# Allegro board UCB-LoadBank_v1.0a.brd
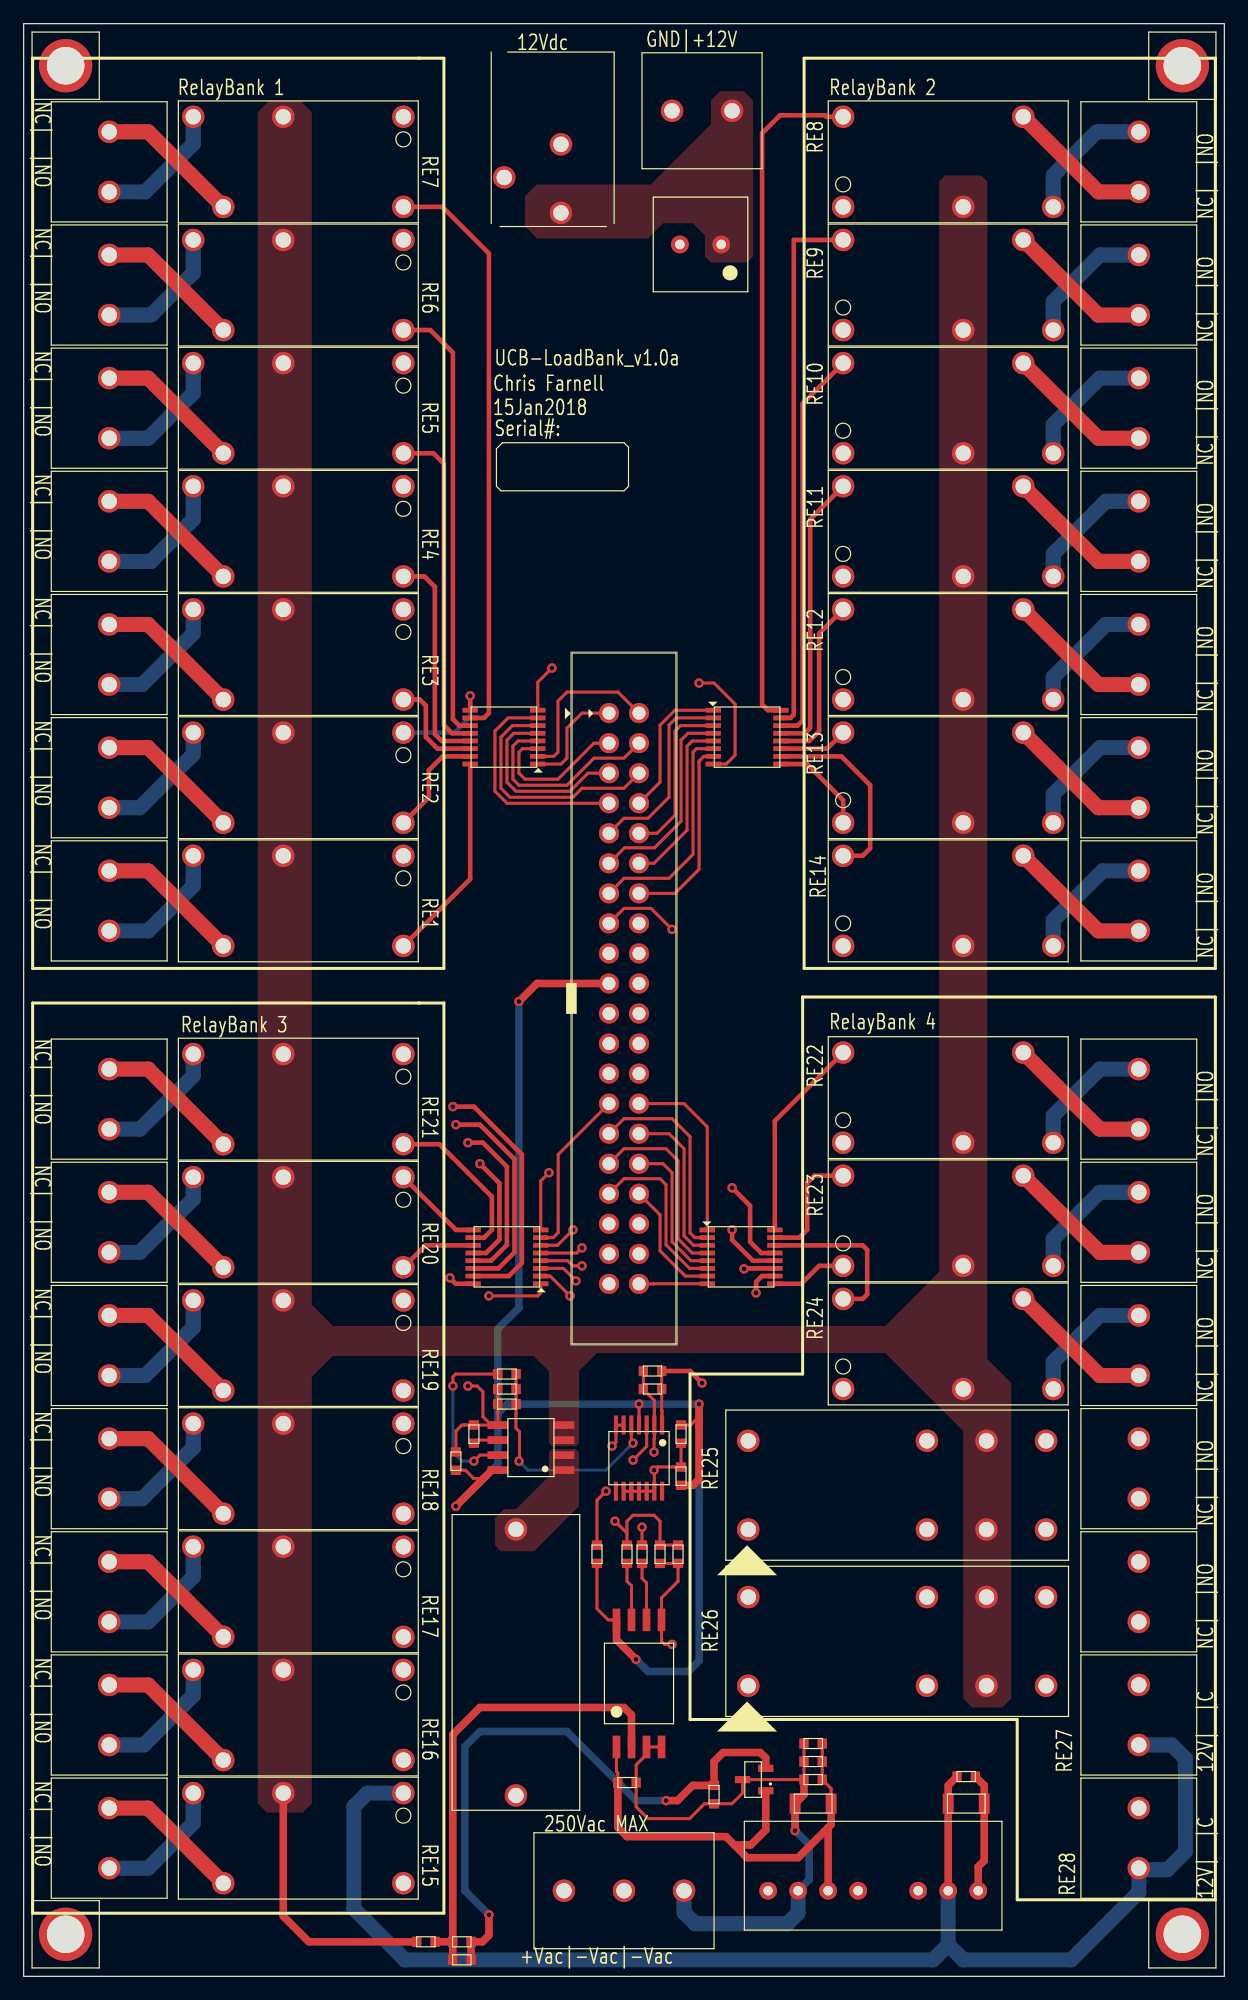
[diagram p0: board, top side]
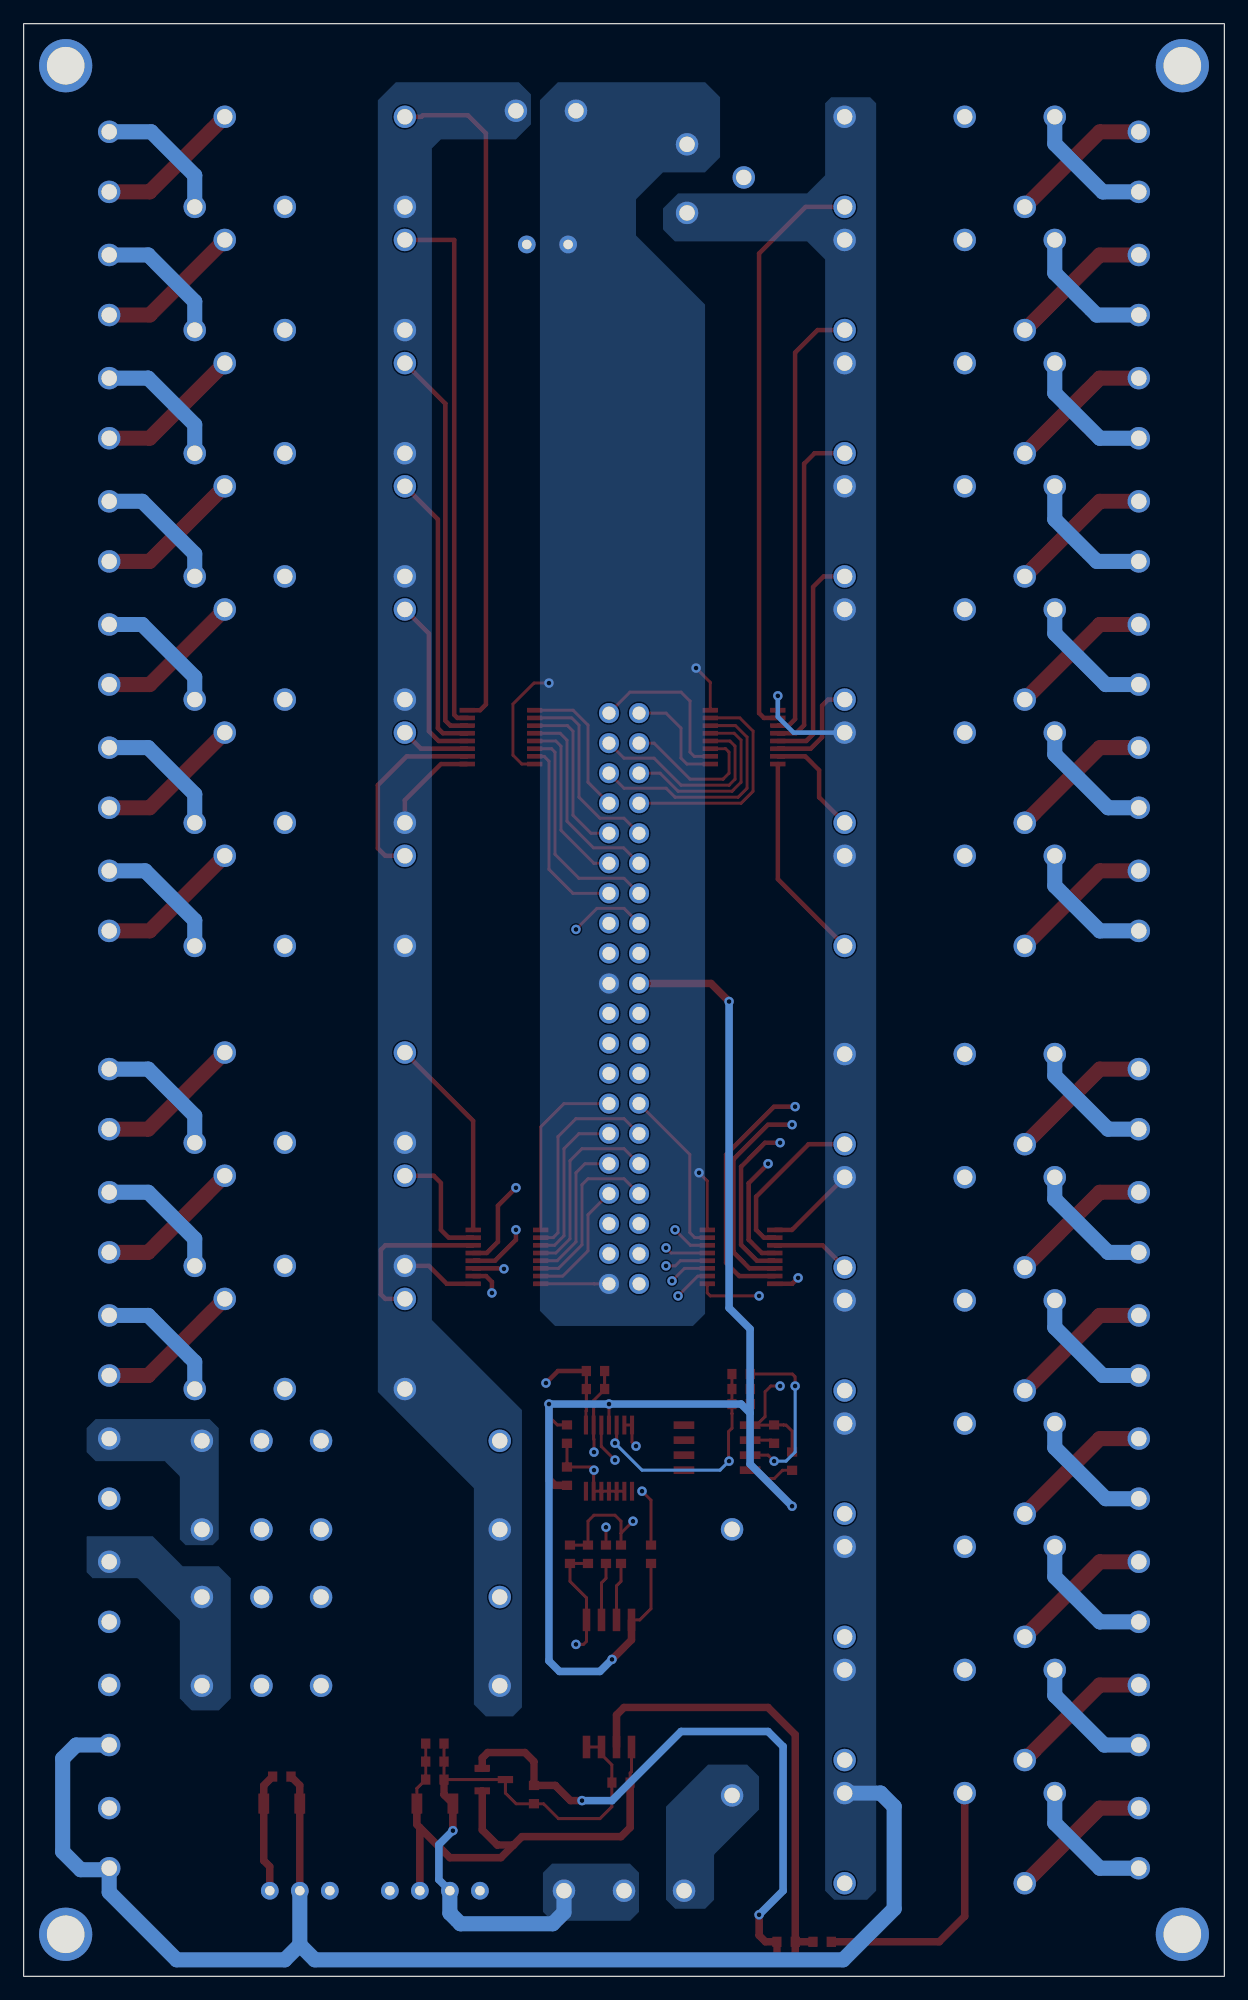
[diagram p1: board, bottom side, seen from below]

Outline 101.6 x 165.1 mm; copper layers: TOP, LAYER_2, LAYER_3, BOTTOM. Coordinates in mm from the lower left corner of the outline.
Outline path: rectangle 0,0 101.6,165.1

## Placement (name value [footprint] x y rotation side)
C1  100uF  [UVZ1H101MPD]  57.28 146.43 180 top
C2  10uF  [C_1206]  66.8 14.6 180 top
C3  1uF  [C_0603]  66.8 16.64 180 top
C4  10uF  [C_1206]  79.76 14.6 0 top
C5  1uF  [C_0603]  79.76 16.89 0 top
C6  1uF  [C_0603]  66.8 18.16 180 top
C7  0.1uF  [C_0603]  66.8 19.69 180 top
C8  0.1uF  [C_0603]  58.42 15.37 270 top
C9  1nF  [C_0603]  38.1 45.85 90 top
C10  0.1uF  [C_0603]  36.58 43.56 90 top
C11  220pF  [C_0603]  40.89 48.39 180 top
C12  1uF  [C_0603]  55.63 42.29 90 top
C13  0.1uF  [C_0603]  55.63 45.85 270 top
C14  100pF  [C_0603]  53.21 51.18 0 top
C15  100pF  [C_0603]  37.08 1.4 0 top
C16  0.1uF  [C_0603]  51.05 16.38 0 top
C17  0.1uF  [C_0603]  48.51 35.69 90 top
C18  100pF  [C_0603]  55.37 35.69 90 top
F1  65600001009  [FUSE_5X20MM]  41.66 26.54 90 top
J1  PJ-102BH  [DC-PWR_JACK]  45.47 155.45 0 top
J2  -  [1715721]  57.4 157.73 270 top
J3  AWHW 40G-0202-T  [40-IDC-M]  50.8 82.68 0 top
J4  -  [1715734]  50.8 7.24 90 top
J5  -  [1715721]  7.24 90.93 0 top
J6  -  [1715721]  7.24 101.35 0 top
J7  -  [1715721]  7.24 111.76 0 top
J8  -  [1715721]  7.24 122.17 0 top
J9  -  [1715721]  7.24 132.59 0 top
J10  -  [1715721]  7.24 143 0 top
J11  -  [1715721]  7.24 153.42 0 top
J12  -  [1715721]  94.36 153.42 180 top
J13  -  [1715721]  94.36 143 180 top
J14  -  [1715721]  94.36 132.59 180 top
J15  -  [1715721]  94.36 122.17 180 top
J16  -  [1715721]  94.36 111.76 180 top
J17  -  [1715721]  94.36 101.35 180 top
J18  -  [1715721]  94.36 90.93 180 top
J19  -  [1715721]  7.24 11.68 0 top
J20  -  [1715721]  7.24 22.1 0 top
J21  -  [1715721]  7.24 32.51 0 top
J22  -  [1715721]  7.24 42.93 0 top
J23  -  [1715721]  7.24 53.34 0 top
J24  -  [1715721]  7.24 63.75 0 top
J25  -  [1715721]  7.24 74.17 0 top
J26  -  [1715721]  94.36 74.17 180 top
J27  -  [1715721]  94.36 63.75 180 top
J28  -  [1715721]  94.36 53.34 180 top
J29  -  [1715721]  94.36 42.93 180 top
J30  -  [1715721]  94.36 32.51 180 top
J31  -  [1985865]  94.36 22.1 180 top
J32  -  [1985865]  94.36 11.68 180 top
LS1  G5SB-14-DC12  [G5SB]  23.24 90.93 270 top
LS2  G5SB-14-DC12  [G5SB]  23.24 101.35 270 top
LS3  G5SB-14-DC12  [G5SB]  23.24 111.76 270 top
LS4  G5SB-14-DC12  [G5SB]  23.24 122.17 270 top
LS5  G5SB-14-DC12  [G5SB]  23.24 132.59 270 top
LS6  G5SB-14-DC12  [G5SB]  23.24 143 270 top
LS7  G5SB-14-DC12  [G5SB]  23.24 153.42 270 top
LS8  G5SB-14-DC12  [G5SB]  78.23 153.42 90 top
LS9  G5SB-14-DC12  [G5SB]  78.23 143 90 top
LS10  G5SB-14-DC12  [G5SB]  78.23 132.59 90 top
LS11  G5SB-14-DC12  [G5SB]  78.23 122.17 90 top
LS12  G5SB-14-DC12  [G5SB]  78.23 111.76 90 top
LS13  G5SB-14-DC12  [G5SB]  78.23 101.35 90 top
LS14  G5SB-14-DC12  [G5SB]  78.23 90.93 90 top
LS15  G5SB-14-DC12  [G5SB]  23.24 11.68 270 top
LS16  G5SB-14-DC12  [G5SB]  23.24 22.1 270 top
LS17  G5SB-14-DC12  [G5SB]  23.24 32.51 270 top
LS18  G5SB-14-DC12  [G5SB]  23.24 42.93 270 top
LS19  G5SB-14-DC12  [G5SB]  23.24 53.34 270 top
LS20  G5SB-14-DC12  [G5SB]  23.24 63.75 270 top
LS21  G5SB-14-DC12  [G5SB]  23.24 74.17 270 top
LS22  G5SB-14-DC12  [G5SB]  78.23 74.29 90 top
LS23  G5SB-14-DC12  [G5SB]  78.23 63.88 90 top
LS24  G5SB-14-DC12  [G5SB]  78.23 53.47 90 top
LS25  RT314012  [TE_RT1-FORMC_5MM]  73.91 41.53 90 top
LS26  RT314012  [TE_RT1-FORMC_5MM]  73.91 28.32 90 top
MECH1  Mech_Hole  [4-40_SCREW]  3.56 161.54 0 top
MECH2  Mech_Hole  [4-40_SCREW]  98.04 161.54 0 top
MECH3  Mech_Hole  [4-40_SCREW]  98.04 3.56 0 top
MECH4  Mech_Hole  [4-40_SCREW]  3.56 3.56 0 top
PM1  EC4SAW-24S05N  [SIP-8]  71.88 8.51 270 top
R1  10k  [R_0603]  40.89 50.93 0 top
R2  15k  [R_0603]  40.89 49.66 180 top
R3  10k  [R_0603]  53.21 49.66 0 top
R4  1Meg  [R_0603]  34.04 2.92 0 top
R5  10k  [R_0603]  51.05 35.69 90 top
R6  2.43k  [R_0603]  37.08 2.92 0 top
R7  10k  [R_0603]  52.32 35.69 90 top
R8  10k  [R_0603]  53.85 35.69 90 top
U1  ISL21080  [SOT_23-3]  61.72 16.64 180 top
U2  ACS714ELCTR-30A-T  [8-SOIC]  42.93 44.7 180 top
U3  OPA4322AIPWR  [OPA4332_14-TSSOP]  52.07 43.81 270 top
U4  ULN2003AIPWR  [16-TSSOP]  40.64 104.77 180 top
U5  ACPL-C87B  [ACPL-C87X]  52.07 24.76 90 top
U6  ULN2003AIPWR  [16-TSSOP]  61.21 104.77 0 top
U7  ULN2003AIPWR  [16-TSSOP]  40.89 60.83 180 top
U8  ULN2003AIPWR  [16-TSSOP]  60.71 60.83 0 top

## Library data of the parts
C1 = CAP P
C2-C18 = CAP NP
F1 = FUSEHOLDER
J1 = DC-Jack_3
J2 J5-J32 = Connector-2
J3 = Header_2x20
J4 = Connector-3
LS1-LS24 = RELAY SPDT
LS25 LS26 = RELAY-SPDT_TE-RT1_16A
MECH1-MECH4 = Mech_Hole
PM1 = EC4SA
R1-R8 = R-Standard
U1 = ISL21080
U2 = ACS714
U3 = OPA4322AIPWR
U4 U6-U8 = ULN2003AI
U5 = ACPL-C87B

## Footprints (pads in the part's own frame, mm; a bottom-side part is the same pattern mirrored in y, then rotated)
4-40_SCREW
  round 4.5 hole 3.175: 1(0,0)
8-SOIC
  rect 1.75x0.65 smd: 1(-2.8,1.905) 2(-2.8,0.635) 3(-2.8,-0.635) 4(-2.8,-1.905) 5(2.8,-1.905) 6(2.8,-0.635) 7(2.8,0.635) 8(2.8,1.905)
16-TSSOP
  rect 1.3x0.4 smd: 1(-2.858,2.275) 2(-2.858,1.625) 3(-2.858,0.975) 4(-2.858,0.325) 5(-2.858,-0.325) 6(-2.858,-0.975) 7(-2.858,-1.625) 8(-2.858,-2.275) 9(2.858,-2.275) 10(2.858,-1.625) 11(2.858,-0.975) 12(2.858,-0.325) 13(2.858,0.325) 14(2.858,0.975) 15(2.858,1.625) 16(2.858,2.275)
40-IDC-M
  round 1.7 hole 1.1: 1(-1.27,24.13) 2(1.27,24.13) 3(-1.27,21.59) 4(1.27,21.59) 5(-1.27,19.05) 6(1.27,19.05) 7(-1.27,16.51) 8(1.27,16.51) 9(-1.27,13.97) 10(1.27,13.97) 11(-1.27,11.43) 12(1.27,11.43) 13(-1.27,8.89) 14(1.27,8.89) 15(-1.27,6.35) 16(1.27,6.35) 17(-1.27,3.81) 18(1.27,3.81) 19(-1.27,1.27) 20(1.27,1.27) 21(-1.27,-1.27) 22(1.27,-1.27) 23(-1.27,-3.81) 24(1.27,-3.81) 25(-1.27,-6.35) 26(1.27,-6.35) 27(-1.27,-8.89) 28(1.27,-8.89) 29(-1.27,-11.43) 30(1.27,-11.43) 31(-1.27,-13.97) 32(1.27,-13.97) 33(-1.27,-16.51) 34(1.27,-16.51) 35(-1.27,-19.05) 36(1.27,-19.05) 37(-1.27,-21.59) 38(1.27,-21.59) 39(-1.27,-24.13) 40(1.27,-24.13)
1715721
  round 1.9 hole 1.3: 1(0,2.54) 2(0,-2.54)
1715734
  round 1.9 hole 1.3: 1(0,5.08) 2(0,0) 3(0,-5.08)
1985865
  round 1.9 hole 1.3: 1(0,2.54) 2(0,-2.54)
ACPL-C87X
  rect 1.905x0.64 smd: 1(-5.372,1.905) 2(-5.372,0.635) 3(-5.372,-0.635) 4(-5.372,-1.905) 5(5.372,-1.905) 6(5.372,-0.635) 7(5.372,0.635) 8(5.372,1.905)
C_0603
  rect 0.787x0.864 smd: 1(-0.775,0) 2(0.775,0)
C_1206
  rect 0.914x1.702 smd: 1(-1.524,0) 2(1.524,0)
DC-PWR_JACK
  round 1.9 hole 1.3: 1(0,-6.35) 2(0,-0.55) 3(-4.8,-3.35)
FUSE_5X20MM
  round 1.9 hole 1.3: 1(-11.25,0) 2(11.25,0)
G5SB
  round 1.9 hole 1.3: 1(-3.81,8.89) 2(-3.81,-1.27) 3(-3.81,-8.89) 4(3.81,-6.35) 5(3.81,8.89)
OPA4332_14-TSSOP
  rect 1.6x0.35 smd: 1(-2.8,1.95) 2(-2.8,1.3) 3(-2.8,0.65) 4(-2.8,0) 5(-2.8,-0.65) 6(-2.8,-1.3) 7(-2.8,-1.95) 8(2.8,-1.95) 9(2.8,-1.3) 10(2.8,-0.65) 11(2.8,0) 12(2.8,0.65) 13(2.8,1.3) 14(2.8,1.95)
R_0603
  rect 0.787x0.864 smd: 1(-0.775,0) 2(0.775,0)
SIP-8
  round 1.5 hole 0.8: 1(1.27,8.89) 2(1.27,6.35) 3(1.27,3.81) 5(1.27,-1.27) 6(1.27,-3.81) 7(1.27,-6.35) 8(1.27,-8.89)
SOT_23-3
  rect 1.3x0.6 smd: 1(-1.075,0.95) 2(-1.075,-0.95) 3(0.889,0)
TE_RT1-FORMC_5MM
  round 1.9 hole 1.3: 1(-3.75,12.6) 2(3.75,12.6) 3(-3.75,-2.52) 4(3.75,-2.52) 5(-3.75,-7.56) 6(3.75,-7.56) 7(-3.75,-12.6) 8(3.75,-12.6)
UVZ1H101MPD
  round 1.5 hole 0.8: 1(-1.75,0) 2(1.75,0)

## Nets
5V_DSP: C10.1 C12.1 C13.1 C17.1 J3.19 J3.39 U2.8(VCC) U3.4(V+) U5.8(VDD2)
5V_ISO: C2.1 C3.1 C6.1 C7.1 C16.1 PM1.6(+VO) U1.1(V_IN) U5.1(VDD1)
GND_SIGNAL: C1.2 C4.2 C5.2 C9.2 C10.2 C11.2 C12.2 C13.2 C17.2 C18.1 J1.2 J2.2(P2) J3.20 J3.40 PM1.1(-VIN) R2.2 R8.1 U2.5(GND) U3.9(-IN) U3.10(+IN) U3.11(V-) U3.12(+IN) U3.13(-IN) U4.8(E) U5.5(GND2) U6.8(E) U7.8(E) U8.8(E)
VIN: C1.1 C4.1 C5.1 J1.1 J2.1(P1) J31.1(P1) J32.1(P1) LS1.1(COIL1) LS2.1(COIL1) LS3.1(COIL1) LS4.1(COIL1) LS5.1(COIL1) LS6.1(COIL1) LS7.1(COIL1) LS8.1(COIL1) LS9.1(COIL1) LS10.1(COIL1) LS11.1(COIL1) LS12.1(COIL1) LS13.1(COIL1) LS14.1(COIL1) LS15.1(COIL1) LS16.1(COIL1) LS17.1(COIL1) LS18.1(COIL1) LS19.1(COIL1) LS20.1(COIL1) LS21.1(COIL1) LS22.1(COIL1) LS23.1(COIL1) LS24.1(COIL1) LS25.1(A1) LS26.1(A1) PM1.2(+VIN) U4.9(COM) U6.9(COM) U7.9(COM) U8.9(COM)
+VAC_IN: LS1.2(COMMON) LS2.2(COMMON) LS3.2(COMMON) LS4.2(COMMON) LS5.2(COMMON) LS6.2(COMMON) LS7.2(COMMON) LS8.2(COMMON) LS9.2(COMMON) LS10.2(COMMON) LS11.2(COMMON) LS12.2(COMMON) LS13.2(COMMON) LS14.2(COMMON) LS15.2(COMMON) LS16.2(COMMON) LS17.2(COMMON) LS18.2(COMMON) LS19.2(COMMON) LS20.2(COMMON) LS21.2(COMMON) LS22.2(COMMON) LS23.2(COMMON) LS24.2(COMMON) LS25.5(COMMON) LS25.6(COMMON2) LS26.5(COMMON) LS26.6(COMMON2) R4.1 U2.3(I-) U2.4(I-.)
-VAC_IN: C2.2 C3.2 C6.2 C7.2 C8.2 C16.2 J4.2(P2) J4.3(P3) PM1.7(-VO) U1.3(GND) U5.3(SHDN) U5.4(GND1)
ADC-I_IN-3V: J3.16 U3.6(-IN) U3.7(OUT)
ADC-VAC_IN: C14.2 J3.15 R3.2 U3.1(OUT)
I_IN: R1.1 U2.7(VOUT)
RE_1: J3.1 U4.1(1B)
RE_2: J3.2 U4.2(2B)
RE_3: J3.3 U4.3(3B)
RE_4: J3.4 U4.4(4B)
RE_5: J3.5 U4.5(5B)
RE_6: J3.6 U4.6(6B)
RE_7: J3.7 U4.7(7B)
RE_8: J3.8 U6.1(1B)
RE_9: J3.9 U6.2(2B)
RE_10: J3.10 U6.3(3B)
RE_11: J3.11 U6.4(4B)
RE_12: J3.12 U6.5(5B)
RE_13: J3.13 U6.6(6B)
RE_14: J3.14 U6.7(7B)
RE_15: J3.21 U7.1(1B)
RE_16: J3.22 U7.2(2B)
RE_17: J3.23 U7.3(3B)
RE_18: J3.24 U7.4(4B)
RE_19: J3.25 U7.5(5B)
RE_20: J3.26 U7.6(6B)
RE_21: J3.27 U7.7(7B)
RE_22: J3.28 U8.1(1B)
RE_23: J3.29 U8.2(2B)
RE_24: J3.30 U8.3(3B)
RE_25: J3.31 U8.4(4B)
RE_26: J3.32 U8.5(5B)
RE_27: J3.33 U8.6(6B)
RE_28: J3.34 U8.7(7B)
VREF_0V9: C8.1 C15.2 R6.2 U1.2(V_OUT)
N38694: F1.2 U2.1(I+) U2.2(I+.)
N41110: C9.1 U2.6(FILTER)
N283386: C11.1 R1.2 R2.1 U3.5(+IN)
N283722: C18.2 R5.2 R8.2 U3.3(+IN)
N283726: R5.1 U5.7(VOUT+)
N283730: R7.1 U5.6(VOUT-)
N283734: C14.1 R3.1 R7.2 U3.2(-IN)
N283872: C15.1 R4.2 R6.1 U5.2(VIN)
N301218: LS7.5(COIL2) U4.10(7C)
N301328: LS6.5(COIL2) U4.11(6C)
N301340: LS5.5(COIL2) U4.12(5C)
N301511: LS4.5(COIL2) U4.13(4C)
N301526: LS3.5(COIL2) U4.14(3C)
N301538: LS2.5(COIL2) U4.15(2C)
N301550: LS1.5(COIL2) U4.16(1C)
N303080: J5.1(P1) LS1.4(NC)
N303092: J5.2(P2) LS1.3(NO)
N303096: J6.2(P2) LS2.3(NO)
N303100: J6.1(P1) LS2.4(NC)
N303115: J7.2(P2) LS3.3(NO)
N303119: J7.1(P1) LS3.4(NC)
N303134: J8.2(P2) LS4.3(NO)
N303138: J8.1(P1) LS4.4(NC)
N303150: J9.2(P2) LS5.3(NO)
N303154: J9.1(P1) LS5.4(NC)
N303169: J10.2(P2) LS6.3(NO)
N303173: J10.1(P1) LS6.4(NC)
N303185: J11.2(P2) LS7.3(NO)
N303189: J11.1(P1) LS7.4(NC)
N307291: F1.1 J4.1(P1)
N308898: LS14.5(COIL2) U6.10(7C)
N308922: LS13.5(COIL2) U6.11(6C)
N308934: LS12.5(COIL2) U6.12(5C)
N308946: LS11.5(COIL2) U6.13(4C)
N308950: LS10.5(COIL2) U6.14(3C)
N308962: LS9.5(COIL2) U6.15(2C)
N308974: LS8.5(COIL2) U6.16(1C)
N309142: J12.1(P1) LS8.4(NC)
N309154: J12.2(P2) LS8.3(NO)
N309158: J13.2(P2) LS9.3(NO)
N309162: J13.1(P1) LS9.4(NC)
N309174: J14.2(P2) LS10.3(NO)
N309178: J14.1(P1) LS10.4(NC)
N309190: J15.2(P2) LS11.3(NO)
N309194: J15.1(P1) LS11.4(NC)
N309206: J16.2(P2) LS12.3(NO)
N309210: J16.1(P1) LS12.4(NC)
N309222: J17.2(P2) LS13.3(NO)
N309226: J17.1(P1) LS13.4(NC)
N309238: J18.2(P2) LS14.3(NO)
N309242: J18.1(P1) LS14.4(NC)
N310612: LS21.5(COIL2) U7.10(7C)
N310636: LS20.5(COIL2) U7.11(6C)
N310648: LS19.5(COIL2) U7.12(5C)
N310660: LS18.5(COIL2) U7.13(4C)
N310664: LS17.5(COIL2) U7.14(3C)
N310676: LS16.5(COIL2) U7.15(2C)
N310688: LS15.5(COIL2) U7.16(1C)
N310856: J19.1(P1) LS15.4(NC)
N310868: J19.2(P2) LS15.3(NO)
N310872: J20.2(P2) LS16.3(NO)
N310876: J20.1(P1) LS16.4(NC)
N310888: J21.2(P2) LS17.3(NO)
N310892: J21.1(P1) LS17.4(NC)
N310904: J22.2(P2) LS18.3(NO)
N310908: J22.1(P1) LS18.4(NC)
N310920: J23.2(P2) LS19.3(NO)
N310924: J23.1(P1) LS19.4(NC)
N310936: J24.2(P2) LS20.3(NO)
N310940: J24.1(P1) LS20.4(NC)
N310952: J25.2(P2) LS21.3(NO)
N310956: J25.1(P1) LS21.4(NC)
N312350: J32.2(P2) U8.10(7C)
N312374: J31.2(P2) U8.11(6C)
N312390: LS26.2(A2) U8.12(5C)
N312398: LS25.2(A2) U8.13(4C)
N312402: LS24.5(COIL2) U8.14(3C)
N312414: LS23.5(COIL2) U8.15(2C)
N312426: LS22.5(COIL2) U8.16(1C)
N312594: J26.1(P1) LS22.4(NC)
N312606: J26.2(P2) LS22.3(NO)
N312610: J27.2(P2) LS23.3(NO)
N312614: J27.1(P1) LS23.4(NC)
N312626: J28.2(P2) LS24.3(NO)
N312630: J28.1(P1) LS24.4(NC)
N312646: J29.1(P1) LS25.3(NC) LS25.4(NC2)
N314100: J30.2(P2) LS26.7(NO) LS26.8(NO2)
N314280: J29.2(P2) LS25.7(NO) LS25.8(NO2)
N314578: J30.1(P1) LS26.3(NC) LS26.4(NC2)

Pads without a net: J1 3; J3 17 18 35 36 37 38; MECH1 1; MECH2 1; MECH3 1; MECH4 1; PM1 3 5 8; U3 8 14

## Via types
v1: diameter 0.8, hole 0.4, TOP to BOTTOM, 42 vias

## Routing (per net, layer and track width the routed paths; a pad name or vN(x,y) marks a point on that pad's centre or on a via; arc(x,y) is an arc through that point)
5V_DSP: length 151.5
  TOP w0.254: U5.8 49.46,30.14 48.51,31.09 C17.1 ; v1(52.07,48.39) U3.4 ; C10.1 37.39,42.79 38.08,42.09 38.92,42.09 ; 57.15,47.33 56.44,46.62 C13.1
  TOP w0.635: v1(57.15,48.39) 57.15,42.04 56.63,41.52 C12.1 ; J3.19 43.43,83.95 v1(41.91,82.42) ; v1(51.82,26.8) 50.17,28.45 U5.8 ; U2.8 39.62,42.8 v1(36.58,39.75)
  LAYER_3 w0.635: J3.39 49.53,56.51 40.13,47.12 40.13,43.31 v1(36.58,39.75)
  BOTTOM w0.635: v1(51.82,26.8) 52.83,25.78 56.26,25.78 57.15,26.67 v1(57.15,48.39) v1(52.07,48.39) 40.89,48.39 40.13,47.62 ; 40.13,47.62 40.13,54.74 41.91,56.51 v1(41.91,82.42) ; 40.13,47.62 40.13,43.31 v1(36.58,39.75)
5V_ISO: length 46.1
  TOP w0.254: C7.1 C6.1 C3.1 68.33,15.89 C2.1 ; U5.1 50.17,17.31 50.28,17.2 C16.1
  TOP w0.635: 60.14,11.11 61.53,11.11 62.8,12.38 U1.1 ; 60.14,11.11 59.44,11.81 51.05,11.81 50.28,12.59 C16.1 ; 60.14,11.11 61.21,10.03 65.53,10.03 68.07,12.57 ; 68.07,12.57 PM1.6 ; 68.07,12.57 68.33,12.83 C2.1
GND_SIGNAL: length 71.9
  TOP w0.254: v1(57.15,109.35) 58.42,109.35 60.2,107.57 60.2,103.25 59.45,102.5 U6.8 ; v1(44.7,110.62) 43.5,109.41 U4.8 ; R2.2 C11.2 40.12,47.57 40.13,47.57 U2.5 39.58,46.61 ; R8.1 C18.1 55.37,33.4 53.98,32 U5.5 53.98,28.32 54.23,28.07 v1(54.86,28.07) ; 39.58,46.61 38.11,46.61 C9.2 37.29,46.62 37.27,46.61 37.08,46.61 36.58,46.1 C10.2 ; 39.58,46.61 38.86,47.32 38.86,49.42 38.37,49.91 v1(37.59,49.91) ; U3.9 U3.10 U3.11 U3.12 U3.13 53.37,42.77 v1(53.34,42.8) 53.61,43.07 C12.2 C13.2 ; C17.2 48.51,40.26 v1(49.28,41.02) ; U7.8 43.75,67.25 v1(44.45,67.94) ; U8.8 53.31,58.56 53.3,58.55 J3.40
  TOP w0.635: PM1.1 80.77,9.27 81.28,9.78 C4.2 81.28,16.14 C5.2
VIN: length 150.2
  TOP w0.381: U4.9 v1(37.78,108.27) ; LS20.1 36.59,63.11 U7.9 ; LS23.1 67.31,60.07 65.8,58.56 U8.9 ; LS13.1 69.34,99.44 66.28,102.5 U6.9
  TOP w0.635: PM1.2 C4.1 78.23,16.14 C5.1
  BOTTOM w0.381: v1(37.78,108.27) 37.78,106.49 36.45,105.16 LS2.1
  BOTTOM w1.27: 78.23,2.67 76.96,1.4 32.26,1.4 27.94,5.72 27.94,14.35 29.08,15.49 LS15.1 ; 78.23,2.67 PM1.2 ; 78.23,2.67 79.5,1.4 88.65,1.4 94.36,7.11 J32.1 94.49,9.02 96.77,9.02 98.3,10.54 98.3,18.41 97.15,19.56 J31.1
+VAC_IN: length 22.6
  TOP w0.635: R4.1 24.13,2.92 21.97,5.08 LS15.2
-VAC_IN: length 51.1
  TOP w0.254: U5.4 U5.3 52.7,18.76 51.83,17.88 C16.2 51.83,14.34 52.83,13.33 56.35,13.33 57.61,14.59 C8.2 59.93,14.59 60.83,15.49 60.83,16.64 C3.2 C6.2 C7.2
  TOP w0.635: v1(65.28,12.32) C2.2 66.03,15.35 C3.2
  BOTTOM w0.635: v1(65.28,12.32) 66.47,11.13 66.47,8.17 PM1.7
  BOTTOM w1.27: J4.3 55.88,5.4 56.84,4.44 64.63,4.44 65.53,5.34 PM1.7
ADC-I_IN-3V: length 50.3
  TOP w0.254: v1(49.78,44.83) 50.12,45.17 U3.7 U3.6
  LAYER_3 w0.381: J3.16 54.48,86.61 54.48,55.88 49.02,50.42 49.02,45.59 v1(49.78,44.83)
ADC-VAC_IN: length 54.4
  TOP w0.254: v1(54.86,88.52) 53.09,90.3 50.8,90.3 J3.15 ; U3.1 54.02,47.8 53.99,47.83 R3.2 C14.2
  TOP w0.381: v1(57.4,50.16) 56.39,51.18 C14.2
  LAYER_3 w0.381: v1(57.4,50.16) 57.4,85.98 v1(54.86,88.52)
I_IN: length 14.6
  TOP w0.254: v1(38.1,43.56) 38.61,44.07 U2.7 ; R1.1 36.56,50.93 36.32,50.69 v1(36.32,49.91)
  BOTTOM w0.254: v1(38.1,43.56) 37.08,43.56 36.32,44.32 v1(36.32,49.91)
RE_1: length 9.3
  TOP w0.254: J3.1 47.24,106.81 45.97,105.54 45.97,103 45.48,102.5 U4.1
RE_2: length 14.1
  TOP w0.254: J3.2 50.29,108.58 45.97,108.58 45.21,107.82 45.21,103.5 44.86,103.15 U4.2
RE_3: length 12.6
  TOP w0.254: J3.3 48.26,104.27 45.21,101.22 42.42,101.22 41.91,101.73 41.91,103.5 42.2,103.8 U4.3
RE_4: length 17.4
  TOP w0.254: U4.4 41.84,104.45 41.4,104.01 41.4,101.22 41.91,100.71 45.97,100.71 48.26,103 50.8,103 J3.4
RE_5: length 16
  TOP w0.254: U4.5 41.47,105.1 40.89,104.52 40.89,100.96 41.66,100.2 46.23,100.2 47.75,101.73 J3.5
RE_6: length 20.7
  TOP w0.254: J3.6 50.8,100.46 47.24,100.46 46.48,99.69 41.15,99.69 40.39,100.46 40.39,104.77 41.36,105.75 U4.6
RE_7: length 19.2
  TOP w0.254: J3.7 40.89,99.19 39.88,100.2 39.88,105.28 41,106.4 U4.7
RE_8: length 12.4
  TOP w0.254: U6.1 55.11,107.05 53.85,105.79 53.85,100.96 J3.8
RE_9: length 16.4
  TOP w0.254: J3.9 50.8,97.92 52.83,97.92 54.61,99.69 54.61,105.79 55.22,106.4 U6.2
RE_10: length 14.2
  TOP w0.254: J3.10 53.59,96.65 55.12,98.17 55.12,105.28 55.59,105.75 U6.3
RE_11: length 17.4
  TOP w0.254: J3.11 50.84,95.42 53.38,95.42 55.63,97.66 55.63,104.52 56.21,105.1 U6.4
RE_12: length 14.7
  TOP w0.254: U6.5 56.57,104.45 56.13,104.01 56.13,96.9 53.34,94.11 J3.12
RE_13: length 19
  TOP w0.254: J3.13 50.8,92.84 54.61,92.84 56.64,94.87 56.64,103.5 56.94,103.8 U6.6
RE_14: length 16.4
  TOP w0.254: J3.14 55.12,91.57 57.15,93.6 57.15,102.74 57.56,103.15 U6.7
RE_15: length 36.6
  TOP w0.254: v1(39.37,57.53) 43.5,57.53 43.75,57.78 U7.1
  LAYER_3 w0.254: v1(39.37,57.53) 41.64,59.8 41.64,79.1 43.94,81.41 J3.21
RE_16: length 38.8
  TOP w0.254: v1(46.23,57.53) 44.55,59.21 U7.2
  LAYER_3 w0.254: v1(46.23,57.53) 43.18,57.53 42.14,58.57 42.14,78.59 43.65,80.1 50.76,80.1 J3.22
RE_17: length 33.2
  TOP w0.254: v1(46.74,58.8) 45.68,59.86 U7.3
  LAYER_3 w0.254: v1(46.74,58.8) 43.52,58.8 42.65,59.67 42.65,77.58 43.94,78.87 J3.23
RE_18: length 33.7
  TOP w0.254: U7.4 46.03,60.51 46.46,60.07 v1(47.24,60.07)
  LAYER_3 w0.254: v1(47.24,60.07) 43.67,60.07 43.16,60.58 43.16,76.31 44.45,77.6 50.8,77.6 J3.24
RE_19: length 27.1
  TOP w0.254: U7.5 46.81,61.16 v1(47.24,61.59)
  LAYER_3 w0.254: J3.25 44.7,76.33 43.67,75.29 43.67,61.85 43.92,61.59 v1(47.24,61.59)
RE_20: length 20.6
  TOP w0.254: U7.6 45.17,61.81 v1(46.48,63.12)
  LAYER_3 w0.254: v1(46.48,63.12) 46.48,73.79 47.75,75.06 50.8,75.06 J3.26
RE_21: length 14.3
  TOP w0.254: U7.7 44.81,62.46 45.23,62.88 45.23,69.49 J3.27
RE_22: length 15.3
  TOP w0.254: U8.1 57.85,71.82 55.88,73.79 J3.28
RE_23: length 17.8
  TOP w0.254: U8.2 56.79,62.46 56.39,62.86 56.39,70.99 54.86,72.52 50.8,72.52 J3.29
RE_24: length 14
  TOP w0.254: U8.3 56.68,61.81 55.88,62.61 55.88,69.98 54.61,71.25 J3.30
RE_25: length 16.4
  TOP w0.254: J3.31 50.8,69.98 54.36,69.98 55.37,68.96 55.37,62.36 56.57,61.16 U8.4
RE_26: length 12.6
  TOP w0.254: J3.32 54.1,68.71 54.86,67.94 54.86,62.1 56.46,60.51 U8.5
RE_27: length 15
  TOP w0.254: J3.33 50.8,67.44 53.85,67.44 54.36,66.93 54.36,61.85 56.35,59.86 U8.6
RE_28: length 10.4
  TOP w0.254: U8.7 55.98,59.21 53.85,61.34 53.85,64.39 J3.34
VREF_0V9: length 52.4
  TOP w0.635: C15.2 R6.2 38.82,2.92 39.37,3.47 v1(39.37,5.21) ; U1.2 62.8,18.46 62.33,18.92 59.18,18.92 58.42,18.16 C8.1 56.61,16.14 55.33,14.86 v1(54.36,14.86)
  BOTTOM w0.635: v1(39.37,5.21) 37.34,7.24 37.34,19.43 38.61,20.7 45.97,20.7 51.82,14.86 v1(54.36,14.86)
N41110: length 2.1
  TOP w0.254: C9.1 38.37,45.34 U2.6
N283386: length 20
  TOP w0.254: v1(51.56,45.08) 51.42,45.23 U3.5 ; R1.2 R2.1 C11.1 41.67,47.57 41.66,47.56 41.66,46.35 41.95,46.06 41.95,43.88 41.91,43.83 v1(41.91,43.56)
  BOTTOM w0.254: v1(41.91,43.56) 42.67,42.8 49.28,42.8 v1(51.56,45.08)
N283722: length 19.5
  TOP w0.254: v1(50.04,38.48) 51.05,37.47 ; 51.05,37.47 51.05,38.48 51.56,38.99 53.34,38.99 53.85,38.48 R8.2 C18.2 ; 51.05,37.47 R5.2 ; U3.3 52.72,44.81 v1(51.56,43.65)
  LAYER_3 w0.254: v1(51.56,43.65) 50.04,42.13 50.04,41.36 50.06,41.34 50.06,40.7 50.04,40.68 v1(50.04,38.48)
N283726: length 4.9
  TOP w0.254: U5.7 51.44,33.02 51.05,33.4 R5.1
N283730: length 4.9
  TOP w0.254: R7.1 52.32,33.66 52.7,33.27 U5.6
N283734: length 15.5
  TOP w0.254: v1(53.34,44.32) 53.34,45.4 53.37,45.43 U3.2 53.37,48.69 52.44,49.62 R3.1 C14.1 ; R7.2 v1(52.32,37.97)
  LAYER_3 w0.254: v1(53.34,44.32) 52.32,43.31 v1(52.32,37.97)
N283872: length 39.6
  TOP w0.635: U5.2 51.44,22.1 50.8,22.73 38.61,22.73 36.31,20.43 R6.1 ; R4.2 R6.1 ; R6.1 C15.1
N301218: length 49.5
  TOP w0.381: U4.10 38.96,106.4 39.37,106.81 39.37,145.67 35.43,149.61 LS7.5
N301328: length 37.7
  TOP w0.381: U4.11 36.87,105.75 36.32,106.3 36.32,137.29 34.42,139.19 LS6.5
N301340: length 28.4
  TOP w0.381: U4.12 36.25,105.1 35.56,105.79 35.56,127.89 34.67,128.78 LS5.5
N301511: length 18.7
  TOP w0.381: U4.13 35.38,104.45 34.8,105.03 34.8,117.47 33.91,118.36 LS4.5
N301526: length 8.9
  TOP w0.381: U4.14 35.01,103.8 34.04,104.77 34.04,107.44 33.53,107.95 LS3.5
N301538: length 9.3
  TOP w0.381: LS2.5 34.29,99.69 34.29,101.98 35.46,103.15 U4.15
N301550: length 17.7
  TOP w0.381: LS1.5 37.78,92.77 U4.16
N303080: length 12.3
  TOP w1.27: J5.1 10.54,93.47 LS1.4
N303092: length 11.2
  BOTTOM w1.27: LS1.3 14.35,92.2 10.54,88.39 J5.2
N303096: length 10.8
  BOTTOM w1.27: LS2.3 14.35,103.32 9.84,98.81 J6.2
N303100: length 12.3
  TOP w1.27: 7.24,103.89 10.54,103.89 LS2.4
N303115: length 10.9
  BOTTOM w1.27: LS3.3 14.35,113.54 10.03,109.22 J7.2
N303119: length 12.3
  TOP w1.27: LS3.4 10.54,114.3 J7.1
N303134: length 11.4
  BOTTOM w1.27: LS4.3 14.35,123.19 10.8,119.63 7.24,119.63
N303138: length 12.3
  TOP w1.27: LS4.4 10.54,124.71 J8.1
N303150: length 11.2
  BOTTOM w1.27: LS5.3 14.35,133.86 10.54,130.05 J9.2
N303154: length 12.3
  TOP w1.27: LS5.4 10.54,135.13 J9.1
N303169: length 11.4
  BOTTOM w1.27: J10.2 10.8,140.46 14.35,144.02 LS6.3
N303173: length 12.3
  TOP w1.27: LS6.4 10.54,145.54 J10.1
N303185: length 11.1
  BOTTOM w1.27: LS7.3 14.35,154.94 10.29,150.88 J11.2
N303189: length 12.3
  TOP w1.27: J11.1 10.54,155.96 LS7.4
N308898: length 16.4
  TOP w0.381: U6.10 69.19,103.15 71.63,100.71 71.63,95.38 70.99,94.74 LS14.5
N308922: length 5.8
  TOP w0.381: U6.11 67.99,103.8 LS13.5
N308934: length 14.7
  TOP w0.381: LS12.5 67.31,113.54 67.31,105.28 66.48,104.45 U6.12
N308946: length 24.3
  TOP w0.381: U6.13 66.11,105.1 66.55,105.54 66.55,123.19 LS11.5
N308950: length 33.7
  TOP w0.381: U6.14 65.49,105.75 65.91,106.17 65.91,132.97 LS10.5
N308962: length 45.5
  TOP w0.381: LS9.5 65.17,146.81 65.17,106.67 64.9,106.4 U6.15
N308974: length 57.6
  TOP w0.381: U6.16 62.98,107.05 62.48,107.54 62.48,155.83 64.01,157.35 67.82,157.35 67.95,157.23 LS8.5
N309142: length 12.4
  TOP w1.27: J12.1 90.93,150.88 LS8.4
N309154: length 11.4
  BOTTOM w1.27: J12.2 90.81,155.96 87.12,152.27 LS8.3
N309158: length 11.3
  BOTTOM w1.27: J13.2 91.06,145.54 87.12,141.61 LS9.3
N309162: length 12.4
  TOP w1.27: J13.1 90.93,140.46 LS9.4
N309174: length 11.3
  BOTTOM w1.27: J14.2 91.06,135.13 87.12,131.19 LS10.3
N309178: length 12.4
  TOP w1.27: J14.1 90.93,130.05 LS10.4
N309190: length 11
  BOTTOM w1.27: J15.2 91.57,124.71 87.12,120.27 LS11.3
N309194: length 12.4
  TOP w1.27: 94.36,119.63 90.93,119.63 LS11.4
N309206: length 11
  BOTTOM w1.27: LS12.3 87.12,109.86 91.57,114.3 J16.2
N309210: length 12.4
  TOP w1.27: J16.1 90.93,109.22 LS12.4
N309222: length 11.3
  BOTTOM w1.27: 94.36,103.89 91.06,103.89 87.12,99.95 LS13.3
N309226: length 12.4
  TOP w1.27: LS13.4 90.93,98.81 J17.1
N309238: length 11.1
  BOTTOM w1.27: LS14.3 87.12,89.28 91.31,93.47 J18.2
N309242: length 12.4
  TOP w1.27: J18.1 90.93,88.39 LS14.4
N310612: length 14
  TOP w0.381: LS21.5 35.18,70.36 39.62,65.91 39.62,63.12 38.96,62.46 U7.10
N310636: length 6.7
  TOP w0.381: LS20.5 34,61.81 U7.11
N310648: length 33.7
  TOP w0.381: v1(38.61,68.71) 40.26,67.06 40.26,62.29 39.13,61.16 U7.12
  LAYER_3 w0.381: LS19.5 34.8,52.2 34.8,68.45 35.05,68.71 v1(38.61,68.71)
N310660: length 51.3
  TOP w0.381: U7.13 39.55,60.51 40.89,61.85 40.89,68.45 38.86,70.48 v1(37.59,70.48)
  LAYER_3 w0.381: LS18.5 29.72,41.53 29.72,61.34 33.78,65.4 33.78,69.22 35.05,70.48 v1(37.59,70.48)
N310664: length 69.1
  TOP w0.381: U7.14 40.17,59.86 41.53,61.21 41.53,69.09 38.61,72.01 v1(36.58,72.01)
  LAYER_3 w0.381: LS17.5 28.96,31.88 28.96,69.98 30.99,72.01 v1(36.58,72.01)
N310676: length 85.1
  TOP w0.381: U7.15 41.05,59.21 42.16,60.32 42.16,69.47 38.1,73.53 v1(36.32,73.53)
  LAYER_3 w0.381: v1(36.32,73.53) 30.48,73.53 27.94,70.99 27.94,22.48 LS16.5
N310688: length 55
  TOP w0.381: v1(36.07,59.05) 36.57,58.56 U7.16
  LAYER_3 w0.381: v1(36.07,59.05) 36.07,52.2 34.54,50.67 34.54,10.29 LS15.5
N310856: length 12.3
  TOP w1.27: LS15.4 10.54,14.22 J19.1
N310868: length 11.2
  BOTTOM w1.27: LS15.3 14.35,12.95 10.54,9.14 J19.2
N310872: length 11
  BOTTOM w1.27: LS16.3 14.35,23.75 10.16,19.56 J20.2
N310876: length 12.3
  TOP w1.27: LS16.4 10.54,24.64 7.24,24.64
N310888: length 11.2
  BOTTOM w1.27: 7.24,29.97 10.54,29.97 14.35,33.78 LS17.3
N310892: length 12.3
  TOP w1.27: LS17.4 10.54,35.05 J21.1
N310904: length 10.9
  BOTTOM w1.27: J22.2 10.03,40.39 14.35,44.7 LS18.3
N310908: length 12.3
  TOP w1.27: LS18.4 10.54,45.47 J22.1
N310920: length 11.1
  BOTTOM w1.27: 7.24,50.8 10.29,50.8 14.35,54.86 LS19.3
N310924: length 12.3
  TOP w1.27: J23.1 10.54,55.88 LS19.4
N310936: length 10.8
  BOTTOM w1.27: J24.2 9.84,61.21 14.35,65.73 LS20.3
N310940: length 12.3
  TOP w1.27: LS20.4 10.54,66.29 J24.1
N310952: length 10.8
  BOTTOM w1.27: 7.24,71.63 9.84,71.63 14.35,76.14 LS21.3
N310956: length 12.3
  TOP w1.27: LS21.4 10.54,76.71 J25.1
N312350: length 87.4
  TOP w0.381: U8.10 62.47,59.21 61.98,58.71 v1(61.98,57.78)
  LAYER_3 w0.381: J32.2 96.77,16.64 96.77,25.27 95.76,26.29 93.47,26.29 91.69,24.51 91.69,23.5 88.39,20.19 67.56,20.19 65.53,22.22 65.53,53.21 61.98,56.77 v1(61.98,57.78)
N312374: length 75.1
  TOP w0.381: U8.11 61,59.86 v1(60.96,59.82)
  LAYER_3 w0.381: 94.36,24.64 89.15,19.43 66.8,19.43 64.52,21.72 64.52,52.96 60.96,56.51 v1(60.96,59.82)
N312390: length 38.6
  TOP w0.381: U8.12 61.71,60.51 59.94,62.27 v1(59.94,63.12)
  LAYER_3 w0.381: v1(59.94,63.12) 59.94,56.51 63.5,52.96 63.5,34.26 LS26.2
N312398: length 30.6
  TOP w0.381: v1(59.94,66.67) 61.47,65.15 61.47,62.1 62.41,61.16 U8.13
  LAYER_3 w0.381: v1(59.94,66.67) 58.84,65.57 58.84,56.6 61.31,54.13 LS25.2
N312402: length 13.9
  TOP w0.381: U8.14 70.99,61.81 71.37,61.43 71.37,57.66 70.99,57.28 LS24.5
N312414: length 10.3
  TOP w0.381: U8.15 65.63,62.46 66.29,63.12 66.29,67.08 66.9,67.69 LS23.5
N312426: length 17.4
  TOP w0.381: U8.16 63.56,72.33 LS22.5
N312594: length 12.5
  TOP w1.27: LS22.4 91.06,71.63 94.36,71.63
N312606: length 11.2
  BOTTOM w1.27: LS22.3 87.12,72.77 91.06,76.71 J26.2
N312610: length 11.2
  BOTTOM w1.27: LS23.3 87.12,62.36 91.06,66.29 J27.2
N312614: length 12.5
  TOP w1.27: J27.1 91.06,61.21 LS23.4
N312626: length 11.2
  BOTTOM w1.27: LS24.3 87.12,51.94 91.06,55.88 J28.2
N312630: length 12.5
  TOP w1.27: LS24.4 91.06,50.8 94.36,50.8

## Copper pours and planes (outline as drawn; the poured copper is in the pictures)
GND_SIGNAL on BOTTOM: 47.5,152.53 43.94,152.53 42.67,153.8 42.67,158.88 43.94,160.15 56.39,160.15 57.91,158.62 57.91,56.26 56.64,54.99 44.96,54.99 43.94,56.01 43.94,141.35 49.78,147.19 49.78,150.24
GND_SIGNAL on LAYER_2: 57.91,57.53 55.63,59.82 38.1,59.82 35.56,57.28 35.56,43.31 37.08,41.78 45.21,41.78 48.01,38.99 48.01,27.3 59.69,15.62 69.6,15.62 74.42,10.79 74.42,5.72 75.18,4.95 82.04,4.95 82.8,5.72 82.8,9.27 71.88,20.19 61.21,20.19 57.91,23.5
VIN on TOP: 60.96,159.38 58.93,159.38 58.17,158.62 58.17,156.59 53.09,151.51 43.43,151.51 42.42,150.5 42.42,147.95 43.43,146.94 52.83,146.94 54.1,148.21 56.64,148.21 57.66,147.19 57.66,145.42 58.17,144.91 61.21,144.91 61.72,145.42 61.72,158.62
VIN on BOTTOM: 62.48,21.97 60.2,21.97 59.44,22.73 59.44,47.88 67.06,55.5 67.06,154.56 66.29,155.32 59.94,155.32 58.67,156.59 58.67,159.13 59.69,160.15 70.1,160.15 71.63,158.62 71.63,49.4 63.5,41.28 63.5,22.99
VIN on BOTTOM: 47.5,147.7 47.5,149.48 46.23,150.75 35.31,150.75 33.78,152.27 33.78,158.37 33.27,158.88 29.97,158.88 29.46,158.37 29.46,7.24 30.23,6.48 33.02,6.48 33.78,7.24 33.78,145.16 35.31,146.69 46.48,146.69
+VAC_IN on TOP: 19.81,157.61 20.83,158.62 23.37,158.62 24.38,157.61 24.38,56.77 26.16,54.99 44.7,54.99 46.99,52.7 46.99,45.08 46.74,44.83 44.7,44.83 44.45,45.08 44.45,51.18 43.18,52.45 26.16,52.45 24.38,50.67 24.38,14.6 23.62,13.84 20.57,13.84 19.81,14.6
+VAC_IN on TOP: 46.99,51.18 48.51,52.7 72.9,52.7 79.5,46.1 79.5,23.5 80.26,22.73 82.8,22.73 83.57,23.5 83.57,50.16 81.53,52.2 81.53,151.76 81.03,152.27 77.98,152.27 77.47,151.76 77.47,59.56 72.9,54.99 44.7,54.99 43.18,53.47 43.18,52.45 44.45,51.18
-VAC_IN on BOTTOM: 49.53,5.46 49.53,8.76 50.29,9.53 56.9,9.53 57.66,8.76 57.66,5.46 56.9,4.7 50.29,4.7
N38694 on TOP: 46.99,44.32 46.74,44.58 44.7,44.58 44.45,44.32 44.45,42.29 41.66,39.5 40.64,39.5 39.88,38.73 39.88,36.45 40.39,35.94 43.18,35.94 46.99,39.75
N307291 on BOTTOM: 46.48,5.72 43.94,5.72 43.18,6.48 43.18,10.29 39.37,14.1 39.37,16.89 40.39,17.91 43.69,17.91 47.24,14.35 47.24,6.48
N312646 on LAYER_2: 78.49,44.58 78.49,46.1 77.22,47.37 74.93,47.37 73.91,46.35 73.91,36.45 74.68,35.69 77.47,35.69 78.49,36.7 78.49,38.48 79.76,39.75 91.69,39.75 92.71,38.73 95.5,38.73 96.27,39.5 96.27,42.04 94.74,43.56 79.5,43.56
N314100 on BOTTOM: 87.38,22.48 85.09,22.48 84.07,23.5 84.07,33.66 85.09,34.67 88.14,34.67 90.68,37.21 96.27,37.21 96.27,34.16 95.76,33.66 91.95,33.66 88.39,30.1 88.39,23.5
N314280 on BOTTOM: 87.88,36.45 85.6,36.45 85.09,36.96 85.09,46.35 85.85,47.12 95.5,47.12 96.27,46.35 96.27,44.32 95.5,43.56 89.66,43.56 88.39,42.29 88.39,36.96
N314578 on LAYER_2: 73.91,33.15 73.91,23.75 74.93,22.73 78.23,22.73 78.99,23.5 78.99,25.78 79.76,26.54 88.39,26.54 89.41,27.56 95,27.56 96.01,28.57 96.01,31.11 95,32.13 90.42,32.13 88.39,30.1 79.25,30.1 78.74,30.61 78.74,33.15 77.72,34.16 74.93,34.16

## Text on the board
Ref Des/Silkscreen Top: RelayBank 1 | RelayBank 3 | Chris Farnell | 15Jan2018 | UCB-LoadBank_v1.0a | Serial#: | 12Vdc | +Vac|-Vac|-Vac | 250Vac MAX | GND|+12V | RelayBank 2 | RelayBank 4 | RE25 | RE26 | RE8 | RE9 | RE10 | RE11 | RE12 | RE13 | RE22 | RE23 | RE24 | RE14 | RE27 | RE28 | NC|  |NO | 12V|  |C | RE7 | RE6 | RE5 | RE4 | RE3 | RE2 | RE1 | RE21 | RE20 | RE19 | RE18 | RE17 | RE16 | RE15
